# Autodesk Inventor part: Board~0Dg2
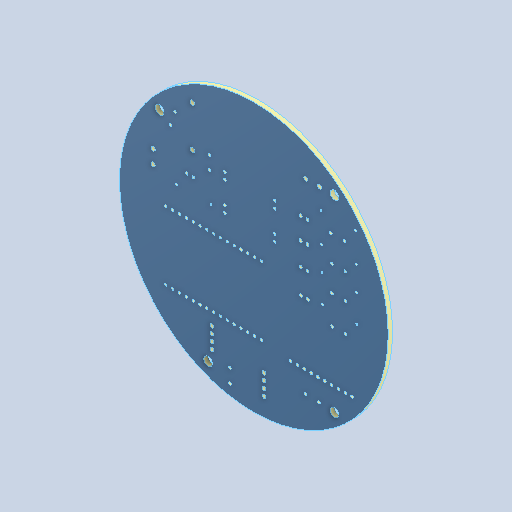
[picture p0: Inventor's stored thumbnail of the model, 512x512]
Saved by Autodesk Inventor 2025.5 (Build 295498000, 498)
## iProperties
Created: 2026-10
Part Number: Board~0Dg2
Material: Genérico
Document SubType Name: Modeling
Designer: Luis M
Density: 1 g/cm^3
Appearance: Valor por defecto
Author: Luis M
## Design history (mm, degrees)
feature "Base1"
node "Sólido1"
